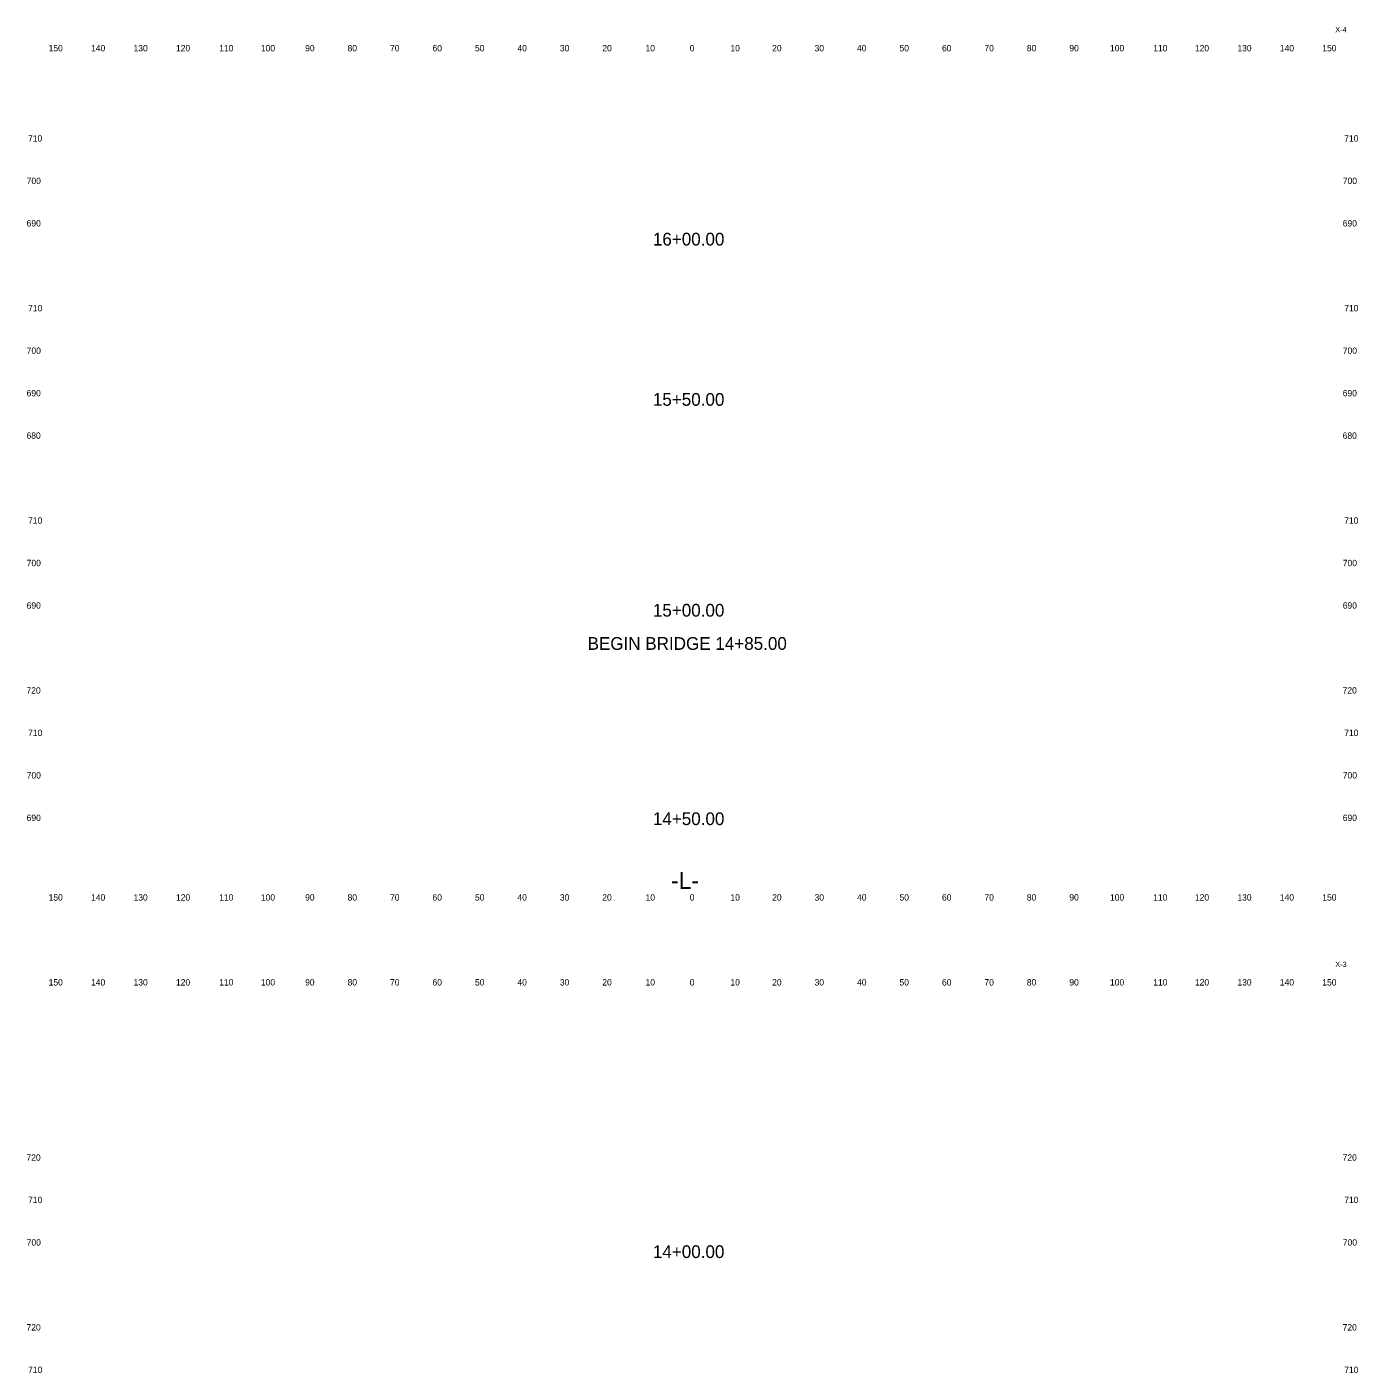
# Model space of a CAD drawing. Extents: x 3 to 317, y 1 to 1307.
# Drawn here: x 3.3 to 316.9, y 330 to 647 of the extents above; entities that cross this region are included whole.
import ezdxf

# ---------------------------------------------------------------- set-up
doc = ezdxf.new("R2010")
doc.units = 0
for name, color, linetype in [('Prop XS Alignment Label', 7, 'Continuous'), ('Prop XS Elevation Labels', 7, 'Continuous'), ('Prop XS Offset Labels', 7, 'Continuous'), ('Prop XS Sheet Number', 7, 'Continuous'), ('Prop XS Station Labels', 7, 'Continuous')]:
    doc.layers.add(name, color=color, linetype=linetype)

msp = doc.modelspace()

# ---------------------------------------------------------------- texts
at = {"layer": 'Prop XS Alignment Label'}
msp.add_text('-L-', height=4, dxfattribs=at).set_placement((155.06, 444))
at = {"layer": 'Prop XS Elevation Labels'}
for s, p in [('710', (3.61, 620)), ('710', (313.61, 620)), ('700', (3.28, 610)), ('700', (313.28, 610)), ('690', (3.26, 600)), ('690', (313.26, 600)), ('710', (3.61, 580)), ('710', (313.61, 580)), ('700', (3.28, 570)), ('700', (313.28, 570)), ('690', (3.26, 560)), ('690', (313.26, 560)), ('680', (3.24, 550)), ('680', (313.24, 550)), ('710', (3.61, 530)), ('710', (313.61, 530)), ('700', (3.28, 520)), ('700', (313.28, 520)), ('690', (3.26, 510)), ('690', (313.26, 510)), ('720', (3.23, 490)), ('720', (313.23, 490)), ('710', (3.61, 480)), ('710', (313.61, 480)), ('700', (3.28, 470)), ('700', (313.28, 470)), ('690', (3.26, 460)), ('690', (313.26, 460)), ('720', (3.23, 380)), ('720', (313.23, 380)), ('710', (3.61, 370)), ('710', (313.61, 370)), ('700', (3.28, 360)), ('700', (313.28, 360)), ('720', (3.23, 340)), ('720', (313.23, 340)), ('710', (3.61, 330)), ('710', (313.61, 330))]:
    msp.add_text(s, height=1.5, dxfattribs=at).set_placement(p)
at = {"layer": 'Prop XS Offset Labels'}
for s, p in [('150', (8.44, 641.25)), ('140', (18.44, 641.25)), ('130', (28.44, 641.25)), ('120', (38.44, 641.25)), ('110', (48.62, 641.25)), ('100', (58.44, 641.25)), ('90', (68.86, 641.25)), ('80', (78.86, 641.25)), ('70', (88.86, 641.25)), ('60', (98.86, 641.25)), ('50', (108.86, 641.25)), ('40', (118.86, 641.25)), ('30', (128.86, 641.25)), ('20', (138.86, 641.25)), ('10', (149.04, 641.25)), ('0', (159.45, 641.25)), ('0', (159.45, 641.25)), ('10', (169.04, 641.25)), ('20', (178.86, 641.25)), ('30', (188.86, 641.25)), ('40', (198.86, 641.25)), ('50', (208.86, 641.25)), ('60', (218.86, 641.25)), ('70', (228.86, 641.25)), ('80', (238.86, 641.25)), ('90', (248.86, 641.25)), ('100', (258.44, 641.25)), ('110', (268.62, 641.25)), ('120', (278.44, 641.25)), ('130', (288.44, 641.25)), ('140', (298.44, 641.25)), ('150', (308.44, 641.25)), ('150', (8.44, 441.25)), ('140', (18.44, 441.25)), ('130', (28.44, 441.25)), ('120', (38.44, 441.25)), ('110', (48.62, 441.25)), ('100', (58.44, 441.25)), ('90', (68.86, 441.25)), ('80', (78.86, 441.25)), ('70', (88.86, 441.25)), ('60', (98.86, 441.25)), ('50', (108.86, 441.25)), ('40', (118.86, 441.25)), ('30', (128.86, 441.25)), ('20', (138.86, 441.25)), ('10', (149.04, 441.25)), ('0', (159.45, 441.25)), ('0', (159.45, 441.25)), ('10', (169.04, 441.25)), ('20', (178.86, 441.25)), ('30', (188.86, 441.25)), ('40', (198.86, 441.25)), ('50', (208.86, 441.25)), ('60', (218.86, 441.25)), ('70', (228.86, 441.25)), ('80', (238.86, 441.25)), ('90', (248.86, 441.25)), ('100', (258.44, 441.25)), ('110', (268.62, 441.25)), ('120', (278.44, 441.25)), ('130', (288.44, 441.25)), ('140', (298.44, 441.25)), ('150', (308.44, 441.25)), ('150', (8.44, 421.25)), ('140', (18.44, 421.25)), ('130', (28.44, 421.25)), ('120', (38.44, 421.25)), ('110', (48.62, 421.25)), ('100', (58.44, 421.25)), ('90', (68.86, 421.25)), ('80', (78.86, 421.25)), ('70', (88.86, 421.25)), ('60', (98.86, 421.25)), ('50', (108.86, 421.25)), ('40', (118.86, 421.25)), ('30', (128.86, 421.25)), ('20', (138.86, 421.25)), ('10', (149.04, 421.25)), ('0', (159.45, 421.25)), ('0', (159.45, 421.25)), ('10', (169.04, 421.25)), ('20', (178.86, 421.25)), ('30', (188.86, 421.25)), ('40', (198.86, 421.25)), ('50', (208.86, 421.25)), ('60', (218.86, 421.25)), ('70', (228.86, 421.25)), ('80', (238.86, 421.25)), ('90', (248.86, 421.25)), ('100', (258.44, 421.25)), ('110', (268.62, 421.25)), ('120', (278.44, 421.25)), ('130', (288.44, 421.25)), ('140', (298.44, 421.25)), ('150', (308.44, 421.25))]:
    msp.add_text(s, height=1.5, dxfattribs=at).set_placement(p)
at = {"layer": 'Prop XS Sheet Number'}
for s, p in [('X-4', (311.5, 645.75)), ('X-3', (311.5, 425.62))]:
    msp.add_text(s, height=1.25, dxfattribs=at).set_placement(p)
at = {"layer": 'Prop XS Station Labels'}
for s, p in [('16+00.00', (150.77, 595.52)), ('15+50.00', (150.77, 557.78)), ('15+00.00', (150.77, 508.12)), ('BEGIN BRIDGE 14+85.00', (135.39, 500.3)), ('14+50.00', (150.77, 459.03)), ('14+00.00', (150.77, 357.07))]:
    msp.add_text(s, height=3, dxfattribs=at).set_placement(p)

doc.saveas('drawing.dxf')
